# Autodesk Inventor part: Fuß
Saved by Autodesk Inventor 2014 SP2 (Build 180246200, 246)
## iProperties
Created: 2015-07
Part Number: Fuß
Material: Generisch
Document SubType Name: Modeling
Designer: e_krauts
Density: 1 g/cm^3
Appearance: Vorgabe
Mass: 34.0103 g
Surface Area: 76.8008 cm^2
Volume: 34.0103 cm^3
Sending System: SolidWorks 2011
Last Author: e_boekem
Sachnummer: NWS 100-00-02
Erstellt durch: XYZ
Werkstoff: AlCu4PbMg
Einheit: Stck.
Author: e_krauts
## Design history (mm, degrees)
node "Fuß.ipt1"
node "Stirnsenkung für M8 Zylinderschraube mit Innensechskant1"
node "Basis1"
